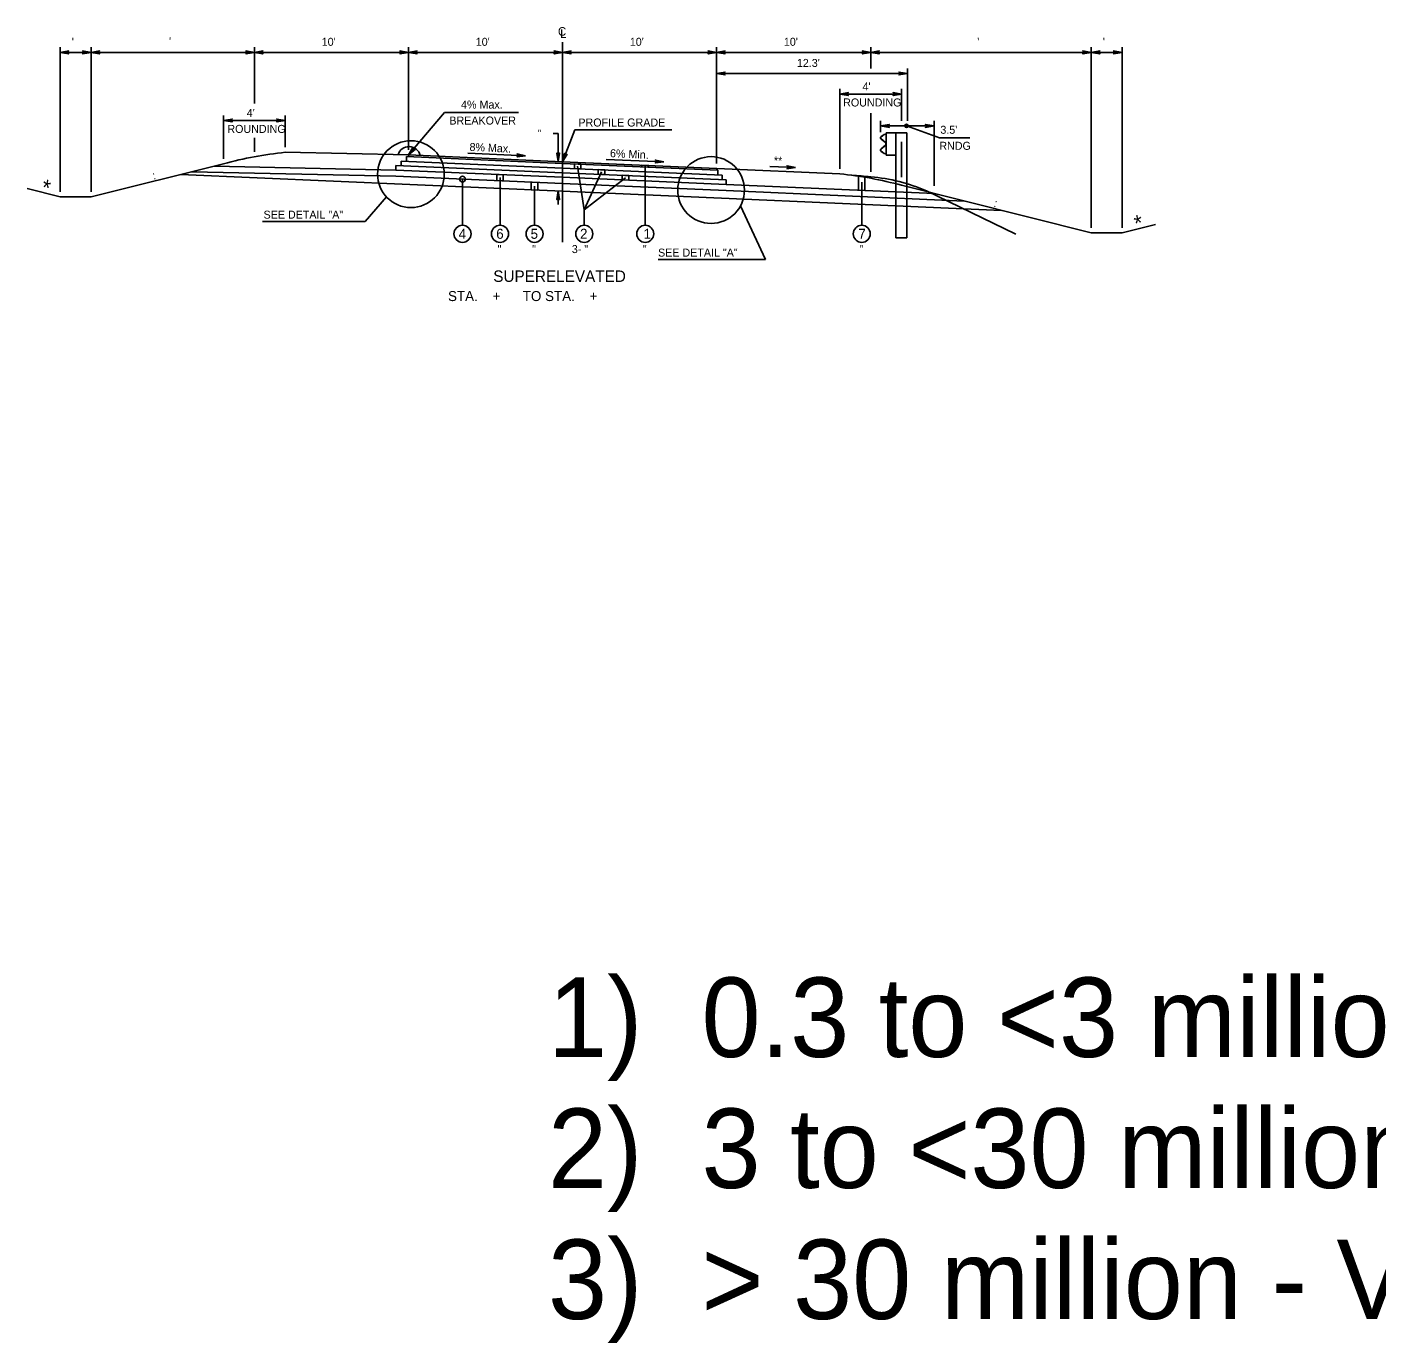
# Model space of a CAD drawing. Extents: x -540 to 1231, y -564 to 421.
# Drawn here: x 488.4 to 724.3, y -487.6 to -257.6 of the extents above; entities that cross this region are included whole.
import ezdxf

# ---------------------------------------------------------------- set-up
doc = ezdxf.new("R2010")
doc.units = 0
doc.layers.add('1', color=7, linetype='Continuous')
doc.layers.add('Des_ Drain_ Ftrs', color=7, linetype='Continuous')

msp = doc.modelspace()

# ---------------------------------------------------------------- linework, layer by layer
at = {"layer": '1'}
for p, q in [((494.2, -286.44), (494.2, -261.17)), ((499.59, -286.44), (499.59, -261.17)), ((528.16, -271), (528.16, -261.17)), ((555.1, -279.1), (555.1, -261.17)), ((582.04, -295.25), (582.04, -260.29)), ((608.98, -281.46), (608.98, -261.17)), ((635.93, -264.87), (635.93, -261.17)), ((674.51, -292.71), (674.51, -261.17)), ((679.9, -292.71), (679.9, -261.17)), ((499.59, -262.05), (494.2, -262.05)), ((528.16, -262.05), (499.59, -262.05)), ((555.1, -262.05), (528.16, -262.05)), ((582.04, -262.05), (555.1, -262.05)), ((582.04, -262.05), (608.98, -262.05)), ((608.98, -262.05), (635.93, -262.05)), ((635.93, -262.05), (674.51, -262.05)), ((674.51, -262.05), (679.9, -262.05)), ((608.98, -265.75), (642.35, -265.75)), ((642.35, -274.03), (642.35, -264.87)), ((630.54, -282.4), (630.54, -268.45)), ((641.31, -274.03), (641.31, -268.45)), ((630.54, -269.33), (641.31, -269.33)), ((522.77, -280.64), (522.77, -273.07)), ((533.55, -278.63), (533.55, -273.07)), ((555.1, -279.98), (561.39, -272.57)), ((574.32, -272.57), (561.39, -272.57)), ((635.93, -282.94), (635.93, -272.67)), ((533.55, -273.95), (522.77, -273.95)), ((582.05, -281.17), (584.2, -275.6)), ((601.12, -275.6), (584.2, -275.6)), ((637.66, -275.98), (637.66, -274.03)), ((637.66, -274.91), (647.04, -274.91)), ((642.18, -274.91), (647.94, -276.98)), ((647.04, -285.39), (647.04, -274.03)), ((528.16, -279.41), (528.16, -277.01)), ((581.29, -276.25), (580.41, -276.25)), ((581.29, -276.25), (581.29, -281.13)), ((637.73, -277.2), (638.49, -277.83)), ((638.49, -278.28), (637.73, -278.92)), ((638.28, -276.38), (637.74, -276.77)), ((637.75, -277.18), (638.51, -277.81)), ((638.51, -278.31), (637.75, -278.94)), ((638.29, -276.41), (637.76, -276.79)), ((638.61, -276.32), (638.28, -276.38)), ((638.61, -276.35), (638.29, -276.41)), ((638.58, -278.02), (638.58, -278.1)), ((638.61, -276.09), (638.61, -280.02)), ((638.61, -276.09), (640.35, -276.09)), ((638.61, -278.02), (638.61, -278.1)), ((640.35, -276.09), (640.35, -294.49)), ((642.25, -276.09), (640.35, -276.09)), ((641.31, -283.85), (641.31, -277.7)), ((642.25, -276.09), (642.25, -294.49)), ((647.94, -276.98), (653.29, -276.98)), ((533.55, -279.51), (555.1, -279.98)), ((582.04, -281.46), (554.76, -280.27)), ((554.76, -281.08), (554.76, -280.27)), ((582.04, -281.16), (555.1, -279.98)), ((555.1, -280.28), (555.1, -279.98)), ((565.46, -279.68), (575.57, -280.12)), ((637.74, -279.35), (638.28, -279.74)), ((637.76, -279.33), (638.29, -279.71)), ((638.28, -279.74), (638.61, -279.8)), ((638.29, -279.71), (638.61, -279.77)), ((638.61, -280.02), (640.35, -280.02)), ((522.77, -281.52), (499.59, -287.32)), ((517.21, -282.92), (552.91, -283.69)), ((521.18, -281.92), (552.91, -282.62)), ((582.04, -283.08), (552.91, -281.81)), ((552.91, -282.62), (552.91, -281.81)), ((552.91, -281.81), (552.91, -281.81)), ((582.04, -283.89), (552.91, -282.62)), ((582.04, -282.27), (553.83, -281.04)), ((553.83, -281.85), (553.83, -281.04)), ((608.99, -282.34), (582.04, -281.16)), ((609.22, -282.65), (582.04, -281.46)), ((609.93, -283.49), (582.04, -282.27)), ((610.63, -284.33), (582.04, -283.08)), ((584.68, -281.97), (585.84, -289.6)), ((588.85, -282.96), (585.84, -289.6)), ((589.64, -280.76), (599.75, -281.2)), ((596.5, -281.95), (596.5, -292.28)), ((630.54, -283.28), (608.99, -282.34)), ((608.99, -282.64), (608.99, -282.34)), ((609.22, -282.65), (609.22, -283.46)), ((622.77, -282.19), (618.27, -282)), ((582.04, -286.31), (515.27, -283.4)), ((582.04, -284.97), (552.91, -283.69)), ((564.54, -284.2), (564.54, -292.28)), ((571.1, -283.95), (571.1, -292.28)), ((577.14, -285.42), (577.14, -292.28)), ((610.63, -285.14), (582.04, -283.89)), ((610.63, -286.22), (582.04, -284.97)), ((593.03, -283.97), (585.84, -289.6)), ((609.93, -283.49), (609.93, -284.3)), ((610.63, -284.33), (610.63, -285.14)), ((610.63, -284.33), (610.63, -284.33)), ((647.07, -286.73), (610.63, -285.14)), ((634.36, -284.73), (634.36, -292.28)), ((637.66, -284.04), (637.66, -284.04)), ((641.31, -285.29), (674.51, -293.59)), ((488.38, -285.86), (494.2, -287.32)), ((499.59, -287.32), (494.2, -287.32)), ((547.49, -291.62), (551.23, -287.3)), ((581.29, -286.28), (581.29, -288.65)), ((658.83, -289.67), (582.04, -286.31)), ((652.3, -288.03), (610.63, -286.22)), ((645.66, -286.27), (661.28, -293.8)), ((585.84, -289.6), (585.84, -292.28)), ((613.16, -288.85), (617.52, -298.25)), ((529.56, -291.62), (547.49, -291.62)), ((685.73, -292.13), (679.9, -293.59)), ((642.25, -294.49), (640.35, -294.49)), ((674.51, -293.59), (679.9, -293.59)), ((598.73, -298.25), (617.52, -298.25))]:
    msp.add_line(p, q, dxfattribs=at)
for points in [[(584.1, -281.55), (585.25, -281.6), (585.25, -282.41), (584.1, -282.36)], [(588.28, -282.54), (589.42, -282.59), (589.42, -283.4), (588.28, -283.35)], [(595.93, -281.77), (597.07, -281.82), (597.07, -282.12), (595.93, -282.07)], [(570.53, -283.39), (571.68, -283.44), (571.68, -284.51), (570.53, -284.46)], [(576.57, -284.73), (577.71, -284.78), (577.71, -286.13), (576.57, -286.08)], [(592.45, -283.53), (593.6, -283.58), (593.6, -284.39), (592.45, -284.34)], [(633.78, -283.69), (634.93, -283.88), (634.93, -286.2), (633.78, -286.15)]]:
    msp.add_lwpolyline(points, close=True, dxfattribs=at)
for centre, radius in [((555.52, -283.34), 5.84), ((608.01, -286.12), 5.84), ((564.54, -284.2), 0.5), ((564.54, -293.77), 1.49), ((571.1, -293.77), 1.49), ((577.14, -293.77), 1.49), ((585.84, -293.77), 1.49), ((596.5, -293.77), 1.49), ((634.36, -293.77), 1.49)]:
    msp.add_circle(centre, radius, dxfattribs=at)
for centre, radius, start, end in [((540.44, -346.35), 67.19, 95.8911, 105.2497), ((555.18, -280.52), 2, 12.9578, 163.1197), ((623.65, -350.11), 67.19, 74.7602, 84.1188)]:
    msp.add_arc(centre, radius, start, end, dxfattribs=at)
msp.add_ellipse((642.18, -274.91), major_axis=(-0.311, 0), ratio=0.964041, dxfattribs=at)
for centre, major_axis, start_param, end_param in [((637.92, -276.99), (-0.288, 0), 5.35781, 7.138763), ((637.92, -276.99), (-0.258, 0), 5.35781, 7.138763), ((638.32, -278.02), (0.258, 0), 0, 0.855848), ((638.32, -278.1), (0.258, 0), 5.427337, 6.283185), ((638.32, -278.02), (0.288, 0), 0, 0.855848), ((638.32, -278.1), (0.288, 0), 5.427337, 6.283185), ((637.92, -279.13), (-0.288, 0), 5.427608, 7.208561), ((637.92, -279.13), (-0.258, 0), 5.427608, 7.208561), ((624.7, -384.48), (105.02, 0), 1.463691, 1.495354), ((633.73, -311.11), (28.39, 0), 1.136862, 1.493152)]:
    msp.add_ellipse(centre, major_axis=major_axis, ratio=0.964041, start_param=start_param, end_param=end_param, dxfattribs=at)
at = {"layer": 'Des_ Drain_ Ftrs'}
for points in [[(494.2, -262.05), (495.69, -262.3), (495.4, -262.05), (495.69, -261.8)], [(499.59, -262.05), (498.1, -262.3), (498.4, -262.05), (498.1, -261.8)], [(499.59, -262.05), (501.08, -262.3), (500.78, -262.05), (501.08, -261.8)], [(528.16, -262.05), (526.67, -262.3), (526.97, -262.05), (526.67, -261.8)], [(528.16, -262.05), (529.65, -262.3), (529.35, -262.05), (529.65, -261.8)], [(555.1, -262.05), (553.61, -262.3), (553.91, -262.05), (553.61, -261.8)], [(555.1, -262.05), (556.59, -262.3), (556.3, -262.05), (556.59, -261.8)], [(582.04, -262.05), (580.55, -262.3), (580.85, -262.05), (580.55, -261.8)], [(582.04, -262.05), (583.53, -262.3), (583.24, -262.05), (583.53, -261.8)], [(608.98, -262.05), (607.5, -262.3), (607.79, -262.05), (607.5, -261.8)], [(608.98, -262.05), (610.47, -262.3), (610.18, -262.05), (610.47, -261.8)], [(635.93, -262.05), (634.44, -262.3), (634.73, -262.05), (634.44, -261.8)], [(635.93, -262.05), (637.41, -262.3), (637.12, -262.05), (637.41, -261.8)], [(674.51, -262.05), (673.02, -262.3), (673.32, -262.05), (673.02, -261.8)], [(674.51, -262.05), (676, -262.3), (675.71, -262.05), (676, -261.8)], [(679.9, -262.05), (678.41, -262.3), (678.71, -262.05), (678.41, -261.8)], [(608.98, -265.75), (610.47, -266), (610.18, -265.75), (610.47, -265.5)], [(642.35, -265.75), (640.86, -266), (641.16, -265.75), (640.86, -265.5)], [(630.54, -269.33), (632.03, -269.58), (631.73, -269.33), (632.03, -269.08)], [(641.31, -269.33), (639.83, -269.58), (640.12, -269.33), (639.83, -269.08)], [(522.77, -273.95), (524.26, -274.19), (523.97, -273.95), (524.26, -273.7)], [(533.55, -273.95), (532.06, -274.19), (532.36, -273.95), (532.06, -273.7)], [(637.66, -274.91), (639.2, -275.16), (638.9, -274.91), (639.2, -274.66)], [(647.04, -274.91), (645.5, -275.16), (645.81, -274.91), (645.5, -274.66)], [(555.1, -279.98), (556.25, -279.01), (555.87, -279.07), (555.87, -278.69)], [(575.57, -280.12), (574.08, -280.3), (574.38, -280.07), (574.1, -279.81)], [(581.29, -281.13), (581.53, -279.64), (581.29, -279.93), (581.04, -279.64)], [(582.05, -281.17), (582.82, -279.87), (582.48, -280.05), (582.35, -279.69)], [(599.75, -281.2), (598.25, -281.38), (598.56, -281.15), (598.28, -280.89)], [(622.77, -282.19), (621.27, -282.38), (621.57, -282.14), (621.29, -281.88)], [(581.29, -286.28), (581.53, -287.77), (581.29, -287.47), (581.04, -287.77)]]:
    msp.add_lwpolyline(points, close=True, dxfattribs=at)

# ---------------------------------------------------------------- texts
at = {"layer": '1'}
for s, height, p in [(" '", 1.4, (495.7, -260.9)), ("  '", 1.4, (512.18, -260.83)), ("10'", 1.4, (539.92, -260.9)), ("10'", 1.4, (566.86, -260.9)), ("10'", 1.4, (593.8, -260.9)), ("10'", 1.4, (620.74, -260.9)), ("  '", 1.4, (653.52, -260.9)), (" '", 1.4, (676.01, -260.9)), ("12.3'", 1.4, (623.02, -264.6)), ("4'", 1.4, (634.5, -268.71)), ('4% Max.', 1.4, (564.29, -271.87)), ('ROUNDING', 1.4, (631.11, -271.51)), ("4'", 1.4, (526.81, -273.33)), ('BREAKOVER', 1.4, (562.24, -274.67)), ('PROFILE GRADE', 1.4, (584.81, -275.01)), ('ROUNDING', 1.4, (523.42, -276.13)), ("3.5'", 1.4, (648.11, -276.28)), ('RNDG', 1.4, (647.93, -279.08)), ('SEE DETAIL "A"', 1.4, (529.75, -291.12)), ('4', 1.75, (563.87, -294.64)), ('6', 1.75, (570.44, -294.64)), ('5', 1.75, (576.45, -294.64)), ('2', 1.75, (585.09, -294.64)), ('1', 1.75, (596.2, -294.64)), ('7', 1.75, (633.77, -294.64)), (' "', 1.4, (570.16, -297.13)), (' "', 1.4, (576.2, -297.13)), ('3- "', 1.4, (583.66, -297.13)), (' "', 1.4, (595.56, -297.13)), ('SEE DETAIL "A"', 1.4, (598.74, -297.75)), ('  "', 1.4, (632.91, -297.13)), ('SUPERELEVATED', 2, (569.92, -302.17)), ('STA.    +      TO STA.    +     ', 1.75, (562.01, -305.52)), ('1)  0.3 to <3 million - Medium traffic volume', 13.8978, (579.49, -437.65)), ('2)  3 to <30 million - Heavy traffic volume', 13.8978, (579.49, -460.55)), ('3)  > 30 million - Very heavy traffic volume (lots of trucks)', 13.8978, (579.49, -483.45))]:
    msp.add_text(s, height=height, dxfattribs=at).set_placement(p)
for s, height, rotation, p in [('  "', 1.4, 0.1438, (576.67, -276.95)), ('8% Max.', 1.4, 357.3761, (565.74, -279.26)), ('6% Min.', 1.4, 357.373, (590.31, -280.36)), ('**', 1.4, 357.2162, (618.95, -281.63)), ('*', 2.8, 347.1521, (490.69, -286.89)), (' : ', 1.4, 14.2282, (510, -284.43)), (' : ', 1.4, 345.7718, (656.86, -288.89)), ('*', 2.8, 12.8479, (682.36, -293.4))]:
    msp.add_text(s, height=height, rotation=rotation, dxfattribs=at).set_placement(p)
at = {"layer": 'Des_ Drain_ Ftrs'}
for s, p in [('C', (581.23, -259.14)), ('L', (581.62, -259.54))]:
    msp.add_text(s, height=1.5, dxfattribs=at).set_placement(p)

doc.saveas('drawing.dxf')
